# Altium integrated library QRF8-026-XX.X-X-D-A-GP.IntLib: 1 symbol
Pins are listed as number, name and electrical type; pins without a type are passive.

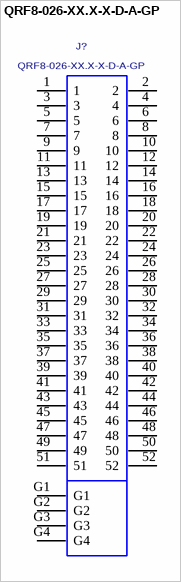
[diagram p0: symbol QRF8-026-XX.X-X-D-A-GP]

## QRF8-026-XX.X-X-D-A-GP
designator J?
0.8MM Q-RATE SOCKET ASSEMBLY; MANUFACTURER: SAMTEC
footprint QRF8-026-XX.X-X-D-A-GP
pins: 1, 2, 3, 4, 5, 6, 7, 8, 9, 10, 11, 12, 13, 14, 15, 16, 17, 18, 19, 20, 21, 22, 23, 24, 25, 26, 27, 28, 29, 30, 31, 32, 33, 34, 35, 36, 37, 38, 39, 40, 41, 42, 43, 44, 45, 46, 47, 48, 49, 50, 51, 52, G1, G2, G3, G4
